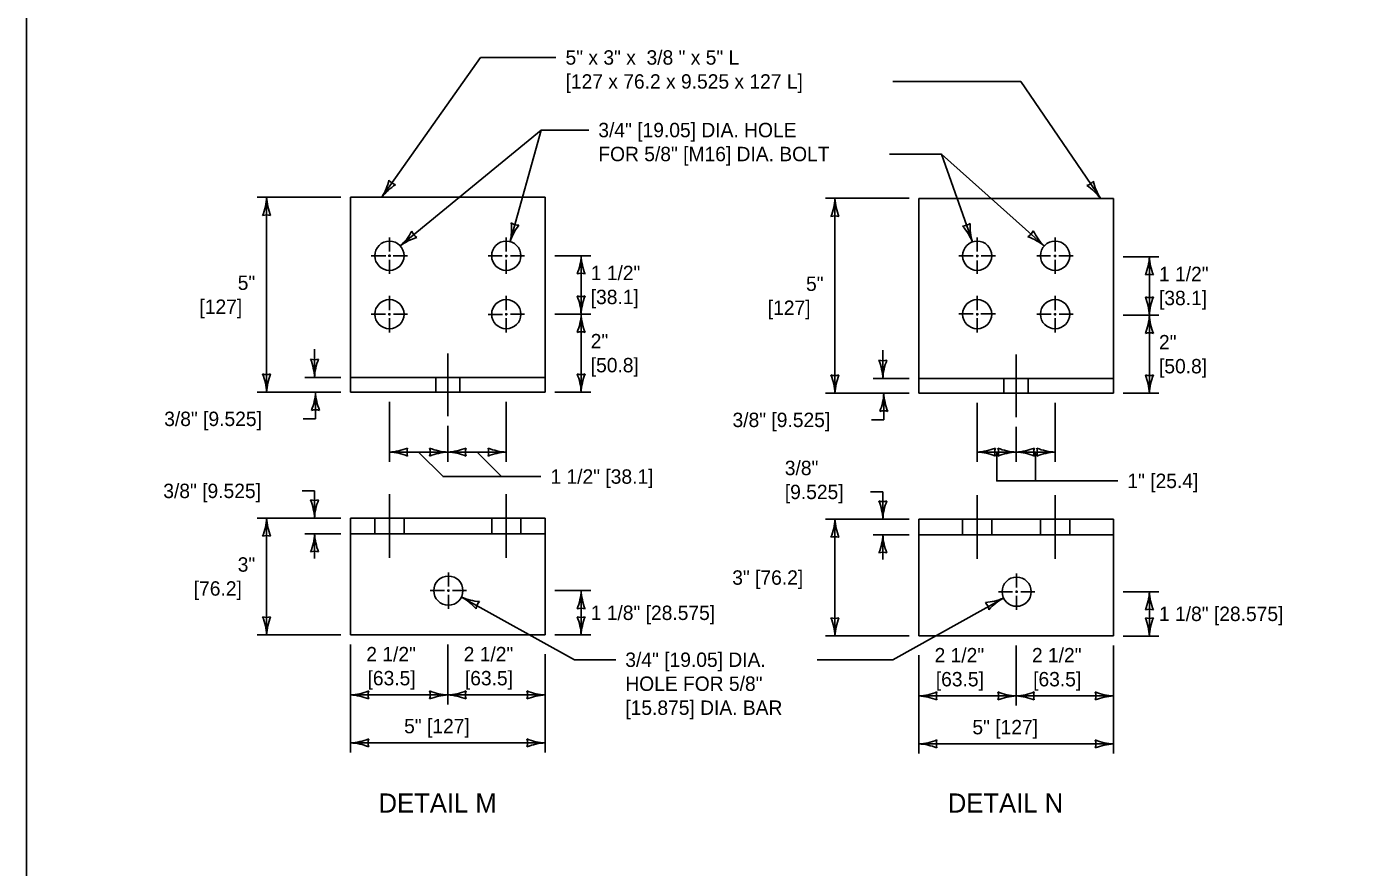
# Model space of a CAD drawing. Extents: x 49991.4 to 50021, y 49987.6 to 50011.4.
# Drawn here: x 49999.38 to 50004.94, y 49991.1 to 49994.61 of the extents above; entities that cross this region are included whole.
import ezdxf

# ---------------------------------------------------------------- set-up
doc = ezdxf.new("R2010")
doc.units = 0
for name, color, linetype in [('Level 1', 7, 'Continuous'), ('Level 2', 7, 'Continuous'), ('Level 3', 7, 'Continuous'), ('Level 4', 7, 'Continuous'), ('Level 5', 7, 'Continuous')]:
    doc.layers.add(name, color=color, linetype=linetype)

msp = doc.modelspace()

# ---------------------------------------------------------------- linework, layer by layer
at = {"layer": 'Level 1'}
for p, q in [((50000.7351, 49993.0864), (50000.7351, 49993.899)), ((50000.7351, 49993.899), (50001.5476, 49993.899)), ((50001.5476, 49993.0864), (50001.5476, 49993.899)), ((50003.1067, 49993.0822), (50003.1067, 49993.8945)), ((50003.1067, 49993.8945), (50003.919, 49993.8945)), ((50003.919, 49993.0822), (50003.919, 49993.8945)), ((50000.7351, 49993.1481), (50001.5476, 49993.1481)), ((50003.1067, 49993.1438), (50003.919, 49993.1438)), ((50000.7351, 49993.0864), (50001.5476, 49993.0864)), ((50003.1067, 49993.0822), (50003.919, 49993.0822)), ((50000.7351, 49992.0738), (50000.7351, 49992.5613)), ((50000.7351, 49992.5613), (50001.5476, 49992.5613)), ((50001.5476, 49992.0738), (50001.5476, 49992.5613)), ((50003.1067, 49992.0695), (50003.1067, 49992.557)), ((50003.1067, 49992.557), (50003.919, 49992.557)), ((50003.919, 49992.0695), (50003.919, 49992.557)), ((50000.7351, 49992.4961), (50001.5476, 49992.4961)), ((50003.1067, 49992.4919), (50003.919, 49992.4919)), ((50000.7351, 49992.0738), (50001.5476, 49992.0738)), ((50003.1067, 49992.0695), (50003.919, 49992.0695))]:
    msp.add_line(p, q, dxfattribs=at)
msp.add_lwpolyline([(49999.3835, 49998.9992), (50016.7501, 49998.9992), (50016.7501, 49987.7988), (49999.3835, 49987.7988)], close=True, dxfattribs=at)
for centre in [(50000.8976, 49993.6552), (50001.3851, 49993.6552), (50003.3504, 49993.6552), (50003.6754, 49993.6552), (50000.8976, 49993.4115), (50001.3851, 49993.4115), (50003.3504, 49993.4115), (50003.6754, 49993.4115), (50001.1435, 49992.2586), (50003.515, 49992.2542)]:
    msp.add_circle(centre, 0.0609, dxfattribs=at)
at = {"layer": 'Level 3'}
for p, q in [((50001.277, 49994.482), (50000.8654, 49993.899)), ((50001.277, 49994.482), (50001.5925, 49994.482)), ((50002.9989, 49994.382), (50003.5321, 49994.382)), ((50003.5321, 49994.382), (50003.8644, 49993.8946)), ((50001.5305, 49994.1794), (50000.9429, 49993.696)), ((50001.5305, 49994.1794), (50001.4015, 49993.7139)), ((50001.7293, 49994.1794), (50001.5305, 49994.1794)), ((50002.9838, 49994.0794), (50003.2013, 49994.0794)), ((50003.2013, 49994.0794), (50003.3302, 49993.7127)), ((50003.2013, 49994.0794), (50003.63, 49993.6959)), ((50000.6951, 49993.899), (50000.3451, 49993.8989)), ((50000.3851, 49993.8989), (50000.3851, 49993.0863)), ((50003.0667, 49993.8947), (50002.7167, 49993.8946)), ((50002.7567, 49993.8946), (50002.7567, 49993.082)), ((50001.7376, 49993.6553), (50001.5876, 49993.6553)), ((50001.6976, 49993.4115), (50001.6976, 49993.6553)), ((50004.109, 49993.651), (50003.959, 49993.651)), ((50004.069, 49993.4072), (50004.069, 49993.651)), ((50001.7376, 49993.4115), (50001.5876, 49993.4115)), ((50001.6976, 49993.4115), (50001.6976, 49993.0864)), ((50004.109, 49993.4072), (50003.959, 49993.4072)), ((50004.069, 49993.4072), (50004.069, 49993.0821)), ((50000.5851, 49993.148), (50000.5851, 49993.2655)), ((50002.9567, 49993.1437), (50002.9567, 49993.2612)), ((50000.6951, 49993.1481), (50000.5451, 49993.148)), ((50003.0667, 49993.1438), (50002.9167, 49993.1437)), ((50000.6951, 49993.0864), (50000.3451, 49993.0863)), ((50000.589, 49993.0864), (50000.589, 49992.975)), ((50000.8975, 49993.0464), (50000.8975, 49992.7964)), ((50001.385, 49993.0464), (50001.385, 49992.7964)), ((50001.5876, 49993.0864), (50001.7376, 49993.0864)), ((50003.0667, 49993.0821), (50002.7167, 49993.082)), ((50002.9606, 49993.0821), (50002.9606, 49992.9707)), ((50003.3504, 49993.0422), (50003.3504, 49992.7964)), ((50003.6753, 49993.0422), (50003.6753, 49992.7964)), ((50003.959, 49993.0821), (50004.109, 49993.0821)), ((50000.589, 49992.975), (50000.5377, 49992.975)), ((50001.1413, 49992.9464), (50001.1413, 49992.7964)), ((50002.9606, 49992.9707), (50002.9093, 49992.9707)), ((50003.5128, 49992.9422), (50003.5128, 49992.7964)), ((50000.8975, 49992.8364), (50001.1413, 49992.8364)), ((50001.1413, 49992.8364), (50001.385, 49992.8364)), ((50001.2631, 49992.8364), (50001.3652, 49992.7344)), ((50003.5128, 49992.8364), (50003.3504, 49992.8364)), ((50003.5128, 49992.8364), (50003.6753, 49992.8364)), ((50003.594, 49992.8364), (50003.594, 49992.7164)), ((50000.5851, 49992.6746), (50000.5338, 49992.6746)), ((50000.5851, 49992.5613), (50000.5851, 49992.6746)), ((50002.9567, 49992.6703), (50002.9054, 49992.6703)), ((50002.9567, 49992.557), (50002.9567, 49992.6703)), ((50000.6951, 49992.5613), (50000.3451, 49992.5613)), ((50000.3851, 49992.5613), (50000.3851, 49992.0738)), ((50003.0667, 49992.557), (50002.7167, 49992.557)), ((50002.7567, 49992.557), (50002.7567, 49992.0695)), ((50000.6951, 49992.4961), (50000.5451, 49992.4961)), ((50000.5851, 49992.4961), (50000.5851, 49992.3924)), ((50003.0667, 49992.4918), (50002.9167, 49992.4918)), ((50002.9567, 49992.4918), (50002.9567, 49992.3881)), ((50001.1981, 49992.2317), (50001.6693, 49991.9706)), ((50001.7376, 49992.2586), (50001.5876, 49992.2586)), ((50001.6976, 49992.0738), (50001.6976, 49992.2586)), ((50002.9982, 49991.9706), (50003.4602, 49992.2276)), ((50004.109, 49992.2542), (50003.959, 49992.2542)), ((50004.069, 49992.0694), (50004.069, 49992.2542)), ((50000.6951, 49992.0738), (50000.3451, 49992.0738)), ((50001.7376, 49992.0738), (50001.5876, 49992.0738)), ((50003.0667, 49992.0695), (50002.7167, 49992.0695)), ((50004.109, 49992.0694), (50003.959, 49992.0694)), ((50000.7351, 49991.5838), (50000.7351, 49992.0338)), ((50001.1413, 49992.0338), (50001.1413, 49991.7838)), ((50001.5476, 49991.5838), (50001.5476, 49991.9938)), ((50003.1065, 49991.5795), (50003.1065, 49991.9895)), ((50003.5127, 49992.0295), (50003.5127, 49991.7795)), ((50003.919, 49991.5795), (50003.919, 49992.0295)), ((50001.6693, 49991.9706), (50001.8419, 49991.9706)), ((50002.9982, 49991.9706), (50002.6829, 49991.9706)), ((50001.1413, 49991.8238), (50000.7351, 49991.8238)), ((50001.1413, 49991.8238), (50001.5476, 49991.8238)), ((50003.5127, 49991.8195), (50003.1065, 49991.8195)), ((50003.5127, 49991.8195), (50003.919, 49991.8195)), ((50000.7351, 49991.6238), (50001.5476, 49991.6238)), ((50003.1065, 49991.6195), (50003.919, 49991.6195))]:
    msp.add_line(p, q, dxfattribs=at)
for points in [[(50001.0194, 49992.8364), (50001.1214, 49992.7344), (50001.5295, 49992.7344)], [(50003.4316, 49992.8364), (50003.4316, 49992.7164), (50003.937, 49992.7164)]]:
    msp.add_lwpolyline(points, dxfattribs=at)
for centre, radius, start, end in [((50000.6687, 49994.0238), 0.233, 327.605, 346.8548), ((50001.0416, 49993.7634), 0.2223, 122.2337, 142.4172), ((50000.9393, 49994.0037), 0.0548, 216.9165, 252.6388), ((50003.7922, 49994.0004), 0.0548, 286.4278, 322.1502), ((50003.6786, 49993.7539), 0.233, 37.1163, 56.3662), ((50004.0531, 49994.0121), 0.2223, 191.745, 211.9285), ((50000.163, 49993.9081), 0.2223, 337.456, 357.6395), ((50000.6178, 49993.9104), 0.233, 182.8273, 202.0772), ((50002.5346, 49993.9038), 0.2223, 337.456, 357.6395), ((50002.9894, 49993.9061), 0.233, 182.8273, 202.0772), ((50000.3851, 49993.7707), 0.0548, 72.1388, 107.8612), ((50002.7567, 49993.7664), 0.0548, 72.1388, 107.8612), ((50001.1741, 49993.7652), 0.233, 347.2975, 6.5473), ((50001.613, 49993.6456), 0.2223, 141.9262, 162.1097), ((50001.4357, 49993.8375), 0.0548, 236.609, 272.3314), ((50003.2877, 49993.8337), 0.0548, 271.5061, 307.2284), ((50003.1145, 49993.6247), 0.233, 22.1946, 41.4444), ((50003.5428, 49993.7778), 0.2223, 176.8233, 197.0068), ((50000.7862, 49993.8684), 0.233, 312.2704, 331.5202), ((50001.0769, 49993.5186), 0.2223, 106.8991, 127.0826), ((50001.0419, 49993.7775), 0.0548, 201.5819, 237.3043), ((50003.5344, 49993.7814), 0.0548, 300.3241, 336.0465), ((50003.4834, 49993.5148), 0.233, 51.0126, 70.2625), ((50003.7849, 49993.8554), 0.2223, 205.6413, 225.8248), ((50001.4755, 49993.6645), 0.2223, 337.456, 357.6395), ((50001.9303, 49993.6668), 0.233, 182.8273, 202.0772), ((50003.8469, 49993.6602), 0.2223, 337.456, 357.6395), ((50004.3017, 49993.6625), 0.233, 182.8273, 202.0772), ((50001.6976, 49993.5271), 0.0548, 72.1388, 107.8612), ((50004.069, 49993.5228), 0.0548, 72.1388, 107.8612), ((50001.6976, 49993.5397), 0.0548, 252.1388, 287.8612), ((50001.4649, 49993.4), 0.233, 2.8273, 22.0772), ((50001.9197, 49993.4023), 0.2223, 157.456, 177.6395), ((50004.069, 49993.5354), 0.0548, 252.1388, 287.8612), ((50003.8363, 49993.3957), 0.233, 2.8273, 22.0772), ((50004.2911, 49993.398), 0.2223, 157.456, 177.6395), ((50001.4755, 49993.4207), 0.2223, 337.456, 357.6395), ((50001.9303, 49993.423), 0.233, 182.8273, 202.0772), ((50003.8469, 49993.4164), 0.2223, 337.456, 357.6395), ((50004.3017, 49993.4187), 0.233, 182.8273, 202.0772), ((50001.6976, 49993.2833), 0.0548, 72.1388, 107.8612), ((50004.069, 49993.279), 0.0548, 72.1388, 107.8612), ((50000.5851, 49993.2762), 0.0548, 252.1388, 287.8612), ((50000.3524, 49993.1365), 0.233, 2.8273, 22.0772), ((50000.8072, 49993.1389), 0.2223, 157.456, 177.6395), ((50002.9567, 49993.2719), 0.0548, 252.1388, 287.8612), ((50002.724, 49993.1322), 0.233, 2.8273, 22.0772), ((50003.1788, 49993.1346), 0.2223, 157.456, 177.6395), ((50000.3851, 49993.2145), 0.0548, 252.1388, 287.8612), ((50000.1524, 49993.0748), 0.233, 2.8273, 22.0772), ((50000.6072, 49993.0772), 0.2223, 157.456, 177.6395), ((50001.6976, 49993.2146), 0.0548, 252.1388, 287.8612), ((50001.4649, 49993.0749), 0.233, 2.8273, 22.0772), ((50001.9197, 49993.0772), 0.2223, 157.456, 177.6395), ((50002.7567, 49993.2102), 0.0548, 252.1388, 287.8612), ((50002.524, 49993.0705), 0.233, 2.8273, 22.0772), ((50002.9788, 49993.0729), 0.2223, 157.456, 177.6395), ((50004.069, 49993.2103), 0.0548, 252.1388, 287.8612), ((50003.8363, 49993.0706), 0.233, 2.8273, 22.0772), ((50004.2911, 49993.0729), 0.2223, 157.456, 177.6395), ((50000.3669, 49993.0955), 0.2223, 337.456, 357.6395), ((50000.8217, 49993.0979), 0.233, 182.8273, 202.0772), ((50002.7385, 49993.0912), 0.2223, 337.456, 357.6395), ((50003.1933, 49993.0936), 0.233, 182.8273, 202.0772), ((50000.589, 49992.9582), 0.0548, 72.1388, 107.8612), ((50002.9606, 49992.9539), 0.0548, 72.1388, 107.8612), ((50000.886, 49993.0691), 0.233, 272.8273, 292.0772), ((50000.8883, 49992.6143), 0.2223, 67.456, 87.6395), ((50001.0257, 49992.8364), 0.0548, 162.1388, 197.8612), ((50001.1505, 49993.0585), 0.2223, 247.456, 267.6395), ((50001.0131, 49992.8364), 0.0548, 342.1388, 17.8612), ((50001.1528, 49992.6037), 0.233, 92.8273, 112.0772), ((50001.1298, 49993.0691), 0.233, 272.8273, 292.0772), ((50001.1321, 49992.6143), 0.2223, 67.456, 87.6395), ((50001.2695, 49992.8364), 0.0548, 162.1388, 197.8612), ((50001.3942, 49993.0585), 0.2223, 247.456, 267.6395), ((50001.2568, 49992.8364), 0.0548, 342.1388, 17.8612), ((50001.3965, 49992.6037), 0.233, 92.8273, 112.0772), ((50003.3389, 49993.0691), 0.233, 272.8273, 292.0772), ((50003.3412, 49992.6143), 0.2223, 67.456, 87.6395), ((50003.4786, 49992.8364), 0.0548, 162.1388, 197.8612), ((50003.522, 49993.0585), 0.2223, 247.456, 267.6395), ((50003.3846, 49992.8364), 0.0548, 342.1388, 17.8612), ((50003.5243, 49992.6037), 0.233, 92.8273, 112.0772), ((50003.5013, 49993.0691), 0.233, 272.8273, 292.0772), ((50003.5036, 49992.6143), 0.2223, 67.456, 87.6395), ((50003.641, 49992.8364), 0.0548, 162.1388, 197.8612), ((50003.6845, 49993.0585), 0.2223, 247.456, 267.6395), ((50003.5471, 49992.8364), 0.0548, 342.1388, 17.8612), ((50003.6868, 49992.6037), 0.233, 92.8273, 112.0772), ((50000.5851, 49992.6895), 0.0548, 252.1388, 287.8612), ((50000.3524, 49992.5498), 0.233, 2.8273, 22.0772), ((50000.8072, 49992.5521), 0.2223, 157.456, 177.6395), ((50002.9567, 49992.6852), 0.0548, 252.1388, 287.8612), ((50002.724, 49992.5455), 0.233, 2.8273, 22.0772), ((50003.1788, 49992.5478), 0.2223, 157.456, 177.6395), ((50000.163, 49992.5705), 0.2223, 337.456, 357.6395), ((50000.6178, 49992.5728), 0.233, 182.8273, 202.0772), ((50002.5346, 49992.5662), 0.2223, 337.456, 357.6395), ((50002.9894, 49992.5685), 0.233, 182.8273, 202.0772), ((50000.3851, 49992.4331), 0.0548, 72.1388, 107.8612), ((50000.363, 49992.5053), 0.2223, 337.456, 357.6395), ((50000.8178, 49992.5076), 0.233, 182.8273, 202.0772), ((50002.7346, 49992.501), 0.2223, 337.456, 357.6395), ((50003.1894, 49992.5033), 0.233, 182.8273, 202.0772), ((50002.7567, 49992.4288), 0.0548, 72.1388, 107.8612), ((50000.5851, 49992.3679), 0.0548, 72.1388, 107.8612), ((50002.9567, 49992.3636), 0.0548, 72.1388, 107.8612), ((50001.0918, 49992.0365), 0.2223, 41.225, 61.4085), ((50001.2907, 49992.4455), 0.233, 246.5963, 265.8461), ((50001.3132, 49992.175), 0.0548, 135.9078, 171.6301), ((50001.4755, 49992.2678), 0.2223, 337.456, 357.6395), ((50001.9303, 49992.2701), 0.233, 182.8273, 202.0772), ((50003.3713, 49992.4314), 0.2223, 273.3656, 293.5491), ((50003.3448, 49992.1716), 0.0548, 8.0484, 43.7708), ((50003.5722, 49992.0233), 0.233, 118.7369, 137.9867), ((50003.8469, 49992.2634), 0.2223, 337.456, 357.6395), ((50004.3017, 49992.2657), 0.233, 182.8273, 202.0772), ((50001.6976, 49992.1304), 0.0548, 72.1388, 107.8612), ((50004.069, 49992.126), 0.0548, 72.1388, 107.8612), ((50000.3851, 49992.202), 0.0548, 252.1388, 287.8612), ((50000.1524, 49992.0623), 0.233, 2.8273, 22.0772), ((50000.6072, 49992.0646), 0.2223, 157.456, 177.6395), ((50001.6976, 49992.202), 0.0548, 252.1388, 287.8612), ((50001.4649, 49992.0623), 0.233, 2.8273, 22.0772), ((50001.9197, 49992.0646), 0.2223, 157.456, 177.6395), ((50002.7567, 49992.1977), 0.0548, 252.1388, 287.8612), ((50002.524, 49992.058), 0.233, 2.8273, 22.0772), ((50002.9788, 49992.0603), 0.2223, 157.456, 177.6395), ((50004.069, 49992.1976), 0.0548, 252.1388, 287.8612), ((50003.8363, 49992.0579), 0.233, 2.8273, 22.0772), ((50004.2911, 49992.0602), 0.2223, 157.456, 177.6395), ((50000.7236, 49992.0565), 0.233, 272.8273, 292.0772), ((50000.7259, 49991.6017), 0.2223, 67.456, 87.6395), ((50000.8633, 49991.8238), 0.0548, 162.1388, 197.8612), ((50001.1505, 49992.0459), 0.2223, 247.456, 267.6395), ((50001.0131, 49991.8238), 0.0548, 342.1388, 17.8612), ((50001.1528, 49991.5911), 0.233, 92.8273, 112.0772), ((50001.1298, 49992.0565), 0.233, 272.8273, 292.0772), ((50001.1321, 49991.6017), 0.2223, 67.456, 87.6395), ((50001.2695, 49991.8238), 0.0548, 162.1388, 197.8612), ((50001.5568, 49992.0459), 0.2223, 247.456, 267.6395), ((50001.4194, 49991.8238), 0.0548, 342.1388, 17.8612), ((50001.5591, 49991.5911), 0.233, 92.8273, 112.0772), ((50003.095, 49992.0522), 0.233, 272.8273, 292.0772), ((50003.0973, 49991.5974), 0.2223, 67.456, 87.6395), ((50003.2347, 49991.8195), 0.0548, 162.1388, 197.8612), ((50003.5219, 49992.0416), 0.2223, 247.456, 267.6395), ((50003.3845, 49991.8195), 0.0548, 342.1388, 17.8612), ((50003.5242, 49991.5868), 0.233, 92.8273, 112.0772), ((50003.5012, 49992.0522), 0.233, 272.8273, 292.0772), ((50003.5035, 49991.5974), 0.2223, 67.456, 87.6395), ((50003.6409, 49991.8195), 0.0548, 162.1388, 197.8612), ((50003.9282, 49992.0416), 0.2223, 247.456, 267.6395), ((50003.7908, 49991.8195), 0.0548, 342.1388, 17.8612), ((50003.9305, 49991.5868), 0.233, 92.8273, 112.0772), ((50000.7236, 49991.8565), 0.233, 272.8273, 292.0772), ((50000.7259, 49991.4017), 0.2223, 67.456, 87.6395), ((50000.8633, 49991.6238), 0.0548, 162.1388, 197.8612), ((50001.5568, 49991.8459), 0.2223, 247.456, 267.6395), ((50001.4194, 49991.6238), 0.0548, 342.1388, 17.8612), ((50001.5591, 49991.3911), 0.233, 92.8273, 112.0772), ((50003.095, 49991.8522), 0.233, 272.8273, 292.0772), ((50003.0973, 49991.3974), 0.2223, 67.456, 87.6395), ((50003.2347, 49991.6195), 0.0548, 162.1388, 197.8612), ((50003.9282, 49991.8416), 0.2223, 247.456, 267.6395), ((50003.7908, 49991.6195), 0.0548, 342.1388, 17.8612), ((50003.9305, 49991.3868), 0.233, 92.8273, 112.0772)]:
    msp.add_arc(centre, radius, start, end, dxfattribs=at)
at = {"layer": 'Level 4'}
for p, q in [((50001.0906, 49993.0864), (50001.0906, 49993.1481)), ((50001.192, 49993.0864), (50001.192, 49993.1481)), ((50003.462, 49993.0822), (50003.462, 49993.1438)), ((50003.5635, 49993.0822), (50003.5635, 49993.1438)), ((50000.8367, 49992.5613), (50000.8367, 49992.4961)), ((50000.9585, 49992.5613), (50000.9585, 49992.4961)), ((50001.3242, 49992.5613), (50001.3242, 49992.4961)), ((50001.446, 49992.5613), (50001.446, 49992.4961)), ((50003.2894, 49992.557), (50003.2894, 49992.4919)), ((50003.4113, 49992.557), (50003.4113, 49992.4919)), ((50003.6144, 49992.557), (50003.6144, 49992.4919)), ((50003.7363, 49992.557), (50003.7363, 49992.4919))]:
    msp.add_line(p, q, dxfattribs=at)
at = {"layer": 'Level 5'}
for p, q in [((50000.8976, 49993.6724), (50000.8976, 49993.7312)), ((50001.3851, 49993.6723), (50001.3851, 49993.7311)), ((50003.3504, 49993.6723), (50003.3504, 49993.7311)), ((50003.6754, 49993.6723), (50003.6754, 49993.7311)), ((50000.8218, 49993.6552), (50000.8821, 49993.6552)), ((50000.8919, 49993.6552), (50000.9029, 49993.6552)), ((50000.8976, 49993.6502), (50000.8976, 49993.6601)), ((50000.9133, 49993.6552), (50000.9736, 49993.6552)), ((50001.3093, 49993.6552), (50001.3685, 49993.6552)), ((50001.3804, 49993.6552), (50001.39, 49993.6552)), ((50001.3851, 49993.6497), (50001.3851, 49993.6596)), ((50001.4021, 49993.6552), (50001.4611, 49993.6552)), ((50003.2744, 49993.6552), (50003.3336, 49993.6552)), ((50003.3457, 49993.6552), (50003.3551, 49993.6552)), ((50003.3504, 49993.6497), (50003.3504, 49993.6596)), ((50003.3672, 49993.6552), (50003.4263, 49993.6552)), ((50003.6569, 49993.655), (50003.5995, 49993.655)), ((50003.6707, 49993.6552), (50003.6803, 49993.6552)), ((50003.6754, 49993.6497), (50003.6754, 49993.6596)), ((50003.6904, 49993.655), (50003.7514, 49993.655)), ((50000.8976, 49993.5793), (50000.8976, 49993.6383)), ((50001.3851, 49993.5792), (50001.3851, 49993.6382)), ((50003.3504, 49993.5792), (50003.3504, 49993.6351)), ((50003.6754, 49993.5792), (50003.6754, 49993.6382)), ((50000.8976, 49993.4287), (50000.8976, 49993.4874)), ((50001.3851, 49993.4287), (50001.3851, 49993.4874)), ((50003.3504, 49993.4287), (50003.3504, 49993.4874)), ((50003.6754, 49993.4287), (50003.6754, 49993.4874)), ((50000.8218, 49993.4115), (50000.881, 49993.4115)), ((50000.8929, 49993.4115), (50000.9025, 49993.4115)), ((50000.8976, 49993.4061), (50000.8976, 49993.416)), ((50000.8976, 49993.3355), (50000.8976, 49993.3945)), ((50000.9146, 49993.4115), (50000.9736, 49993.4115)), ((50001.3695, 49993.4096), (50001.3093, 49993.4096)), ((50001.3804, 49993.4115), (50001.39, 49993.4115)), ((50001.3851, 49993.4061), (50001.3851, 49993.416)), ((50001.3851, 49993.3355), (50001.3851, 49993.3945)), ((50001.4032, 49993.4111), (50001.4611, 49993.4111)), ((50003.334, 49993.4123), (50003.2744, 49993.4123)), ((50003.3457, 49993.4115), (50003.3551, 49993.4115)), ((50003.3504, 49993.4061), (50003.3504, 49993.416)), ((50003.3504, 49993.3355), (50003.3504, 49993.3945)), ((50003.366, 49993.4123), (50003.4263, 49993.4123)), ((50003.5995, 49993.4115), (50003.6588, 49993.4115)), ((50003.6707, 49993.4115), (50003.6803, 49993.4115)), ((50003.6754, 49993.4061), (50003.6754, 49993.416)), ((50003.6754, 49993.3355), (50003.6754, 49993.3945)), ((50003.6923, 49993.4115), (50003.7514, 49993.4115)), ((50001.1413, 49993.2481), (50001.1413, 49992.9864)), ((50003.5128, 49993.2438), (50003.5128, 49992.9822)), ((50000.8975, 49992.6613), (50000.8975, 49992.3961)), ((50001.385, 49992.6613), (50001.385, 49992.3961)), ((50003.3504, 49992.657), (50003.3504, 49992.3919)), ((50003.6753, 49992.657), (50003.6753, 49992.3919)), ((50001.1435, 49992.3345), (50001.1435, 49992.2754)), ((50003.515, 49992.3302), (50003.515, 49992.2712)), ((50001.1435, 49992.2639), (50001.1435, 49992.2539)), ((50001.0676, 49992.2586), (50001.1267, 49992.2586)), ((50001.1388, 49992.2586), (50001.1482, 49992.2586)), ((50001.1435, 49992.2413), (50001.1435, 49992.1826)), ((50001.1605, 49992.2586), (50001.2195, 49992.2586)), ((50003.4391, 49992.2542), (50003.4982, 49992.2542)), ((50003.5103, 49992.2542), (50003.5197, 49992.2542)), ((50003.515, 49992.2597), (50003.515, 49992.2498)), ((50003.515, 49992.2371), (50003.515, 49992.1783)), ((50003.532, 49992.2542), (50003.5909, 49992.2542))]:
    msp.add_line(p, q, dxfattribs=at)

# ---------------------------------------------------------------- texts
at = {"layer": 'Level 2'}
for s, height, p in [('5" x 3" x  3/8 " x 5" L', 0.06, (50001.6325, 49994.452)), ('[127 x 76.2 x 9.525 x 127 L]', 0.06, (50001.6325, 49994.352)), ('3/4" [19.05] DIA. HOLE ', 0.06, (50001.7693, 49994.1494)), ('FOR 5/8" [M16] DIA. BOLT', 0.06, (50001.7693, 49994.0494)), ('1 1/2"', 0.06, (50001.7376, 49993.5534)), ('1 1/2"', 0.06, (50004.109, 49993.5491)), ('5"', 0.06, (50000.2644, 49993.5127)), ('5"', 0.06, (50002.636, 49993.5084)), ('[38.1]', 0.06, (50001.7376, 49993.4534)), ('[38.1]', 0.06, (50004.109, 49993.4491)), ('[127]', 0.06, (50000.1047, 49993.4127)), ('[127]', 0.06, (50002.4763, 49993.4084)), ('2"', 0.06, (50001.7376, 49993.269)), ('2"', 0.06, (50004.109, 49993.2647)), ('[50.8]', 0.06, (50001.7376, 49993.169)), ('[50.8]', 0.06, (50004.109, 49993.1647)), ('3/8" [9.525]', 0.06, (49999.9577, 49992.945)), ('3/8" [9.525]', 0.06, (50002.3293, 49992.9407)), ('1 1/2" [38.1]', 0.06, (50001.5695, 49992.7044)), ('3/8"', 0.06, (50002.5475, 49992.7403)), ('3/8" [9.525]', 0.06, (49999.9538, 49992.6446)), ('1" [25.4]', 0.06, (50003.977, 49992.6864)), ('[9.525]', 0.06, (50002.5475, 49992.6403)), ('3"', 0.06, (50000.2644, 49992.3377)), ('3" [76.2]', 0.06, (50002.3281, 49992.2833)), ('[76.2]', 0.06, (50000.081, 49992.2377)), ('1 1/8" [28.575]', 0.06, (50001.7376, 49992.1362)), ('1 1/8" [28.575]', 0.06, (50004.109, 49992.1319)), ('2 1/2"', 0.06, (50000.8011, 49991.9638)), ('2 1/2"', 0.06, (50001.2074, 49991.9638)), ('3/4" [19.05] DIA.', 0.06, (50001.8819, 49991.9406)), ('2 1/2"', 0.06, (50003.1725, 49991.9595)), ('2 1/2"', 0.06, (50003.5788, 49991.9595)), ('[63.5]', 0.06, (50000.8062, 49991.8638)), ('[63.5]', 0.06, (50001.2124, 49991.8638)), ('HOLE FOR 5/8"', 0.06, (50001.8819, 49991.8406)), ('[63.5]', 0.06, (50003.1776, 49991.8595)), ('[63.5]', 0.06, (50003.5838, 49991.8595)), ('[15.875] DIA. BAR', 0.06, (50001.8819, 49991.7406)), ('5" [127]', 0.06, (50000.9589, 49991.6638)), ('5" [127]', 0.06, (50003.3303, 49991.6595)), ('DETAIL M', 0.08, (50000.852, 49991.333)), ('DETAIL N', 0.08, (50003.2277, 49991.333))]:
    msp.add_text(s, height=height, dxfattribs=at).set_placement(p)

doc.saveas('drawing.dxf')
